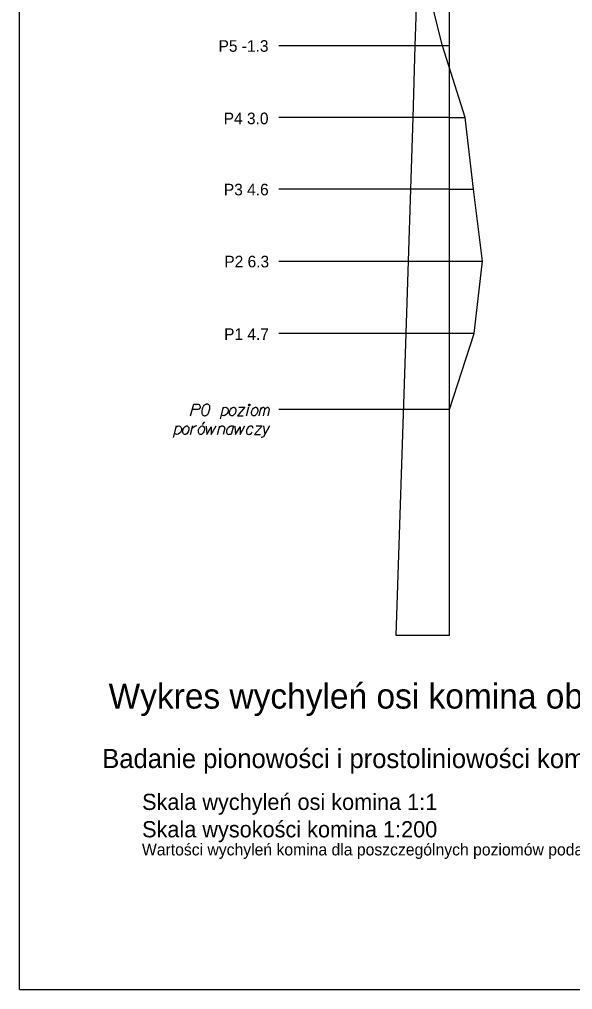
# Model space of a CAD drawing. Extents: x 138 to 6653, y -177 to 1520.
# Drawn here: x 377.01 to 387.51, y 2.29 to 20.71 of the extents above; entities that cross this region are included whole.
import ezdxf

# ---------------------------------------------------------------- set-up
doc = ezdxf.new("R2010")
doc.units = 0
for name, color, linetype in [('15 listopad 2008', 7, 'Continuous'), ('Opisy', 7, 'Continuous'), ('Ramka do drukowania', 7, 'Continuous'), ('Standart wykresów', 7, 'Continuous'), ('Wykresy 4 maj 2008', 7, 'Continuous')]:
    doc.layers.add(name, color=color, linetype=linetype)

msp = doc.modelspace()

# ---------------------------------------------------------------- linework, layer by layer
at = {"layer": '15 listopad 2008'}
msp.add_lwpolyline([(385.168, 13.297), (385.638, 14.742), (385.798, 16.118), (385.628, 17.485), (385.468, 18.843), (385.038, 20.202), (384.688, 21.593), (383.508, 22.995), (383.198, 23.989), (383.168, 24.969), (383.328, 25.428), (383.838, 25.945), (384.008, 26.413), (384.828, 26.981), (386.018, 27.507), (386.078, 27.694), (390.178, 28.392), (392.538, 28.755), (393.608, 29.011)], dxfattribs=at)
at = {"layer": 'Ramka do drukowania'}
for q in [(377.007, 31.985), (398.007, 2.285)]:
    msp.add_line((377.007, 2.285), q, dxfattribs=at)
at = {"layer": 'Standart wykresów'}
for p, q in [((385.168, 9.011), (385.168, 29.095)), ((384.521, 20.202), (384.565, 21.593)), ((385.038, 20.202), (381.931, 20.202)), ((384.478, 18.843), (384.521, 20.202)), ((385.168, 18.843), (381.931, 18.843)), ((384.436, 17.485), (384.478, 18.843)), ((385.168, 17.485), (381.931, 17.485)), ((384.394, 16.118), (384.436, 17.485)), ((385.168, 17.485), (385.628, 17.485)), ((381.931, 16.118), (385.168, 16.118)), ((384.349, 14.742), (384.394, 16.118)), ((385.168, 14.742), (381.931, 14.742)), ((384.161, 9.011), (384.349, 14.742)), ((385.168, 13.297), (381.931, 13.297)), ((385.168, 9.011), (384.161, 9.011))]:
    msp.add_line(p, q, dxfattribs=at)
for points in [[(380.257, 13.181), (380.316, 13.401), (380.39, 13.401), (380.4, 13.399), (380.406, 13.398), (380.416, 13.392), (380.423, 13.387), (380.428, 13.38), (380.433, 13.372), (380.437, 13.36), (380.439, 13.349), (380.437, 13.341), (380.435, 13.334), (380.432, 13.327), (380.428, 13.321), (380.423, 13.315), (380.416, 13.309), (380.411, 13.306), (380.402, 13.302), (380.394, 13.301), (380.29, 13.301)], [(380.572, 13.401), (380.568, 13.401), (380.558, 13.399), (380.551, 13.398), (380.546, 13.396), (380.537, 13.392), (380.527, 13.387), (380.518, 13.382), (380.51, 13.375), (380.504, 13.368), (380.499, 13.36), (380.494, 13.351), (380.489, 13.341), (380.485, 13.334), (380.482, 13.323), (380.477, 13.306), (380.471, 13.28), (380.468, 13.259), (380.468, 13.24), (380.47, 13.226), (380.477, 13.211), (380.482, 13.202), (380.491, 13.192), (380.501, 13.185), (380.506, 13.183), (380.517, 13.181), (380.525, 13.181), (380.539, 13.183), (380.551, 13.186), (380.56, 13.192), (380.572, 13.2), (380.577, 13.205), (380.584, 13.212), (380.589, 13.219), (380.593, 13.224), (380.596, 13.233), (380.598, 13.237), (380.601, 13.245), (380.605, 13.256), (380.608, 13.266), (380.61, 13.273), (380.612, 13.278), (380.614, 13.285), (380.617, 13.301), (380.619, 13.309), (380.62, 13.318), (380.622, 13.33), (380.624, 13.346), (380.624, 13.351), (380.622, 13.358), (380.62, 13.365), (380.615, 13.375), (380.61, 13.382), (380.605, 13.387), (380.598, 13.392), (380.591, 13.396), (380.586, 13.398), (380.581, 13.399), (380.572, 13.401)], [(380.823, 13.124), (380.882, 13.341)], [(380.877, 13.321), (380.894, 13.335), (380.92, 13.341), (380.941, 13.337), (380.955, 13.327), (380.965, 13.313), (380.972, 13.294), (380.974, 13.276), (380.97, 13.261), (380.965, 13.242), (380.951, 13.221), (380.934, 13.202), (380.908, 13.185), (380.885, 13.181), (380.865, 13.183), (380.842, 13.195)], [(381.071, 13.341), (381.083, 13.341), (381.097, 13.334), (381.111, 13.315), (381.112, 13.306), (381.114, 13.297), (381.114, 13.29), (381.114, 13.264), (381.109, 13.247), (381.1, 13.226), (381.09, 13.209), (381.073, 13.193), (381.057, 13.181), (381.031, 13.181), (381.021, 13.185), (381.01, 13.193), (381.005, 13.202), (380.998, 13.223), (380.998, 13.254), (381.002, 13.264), (381.008, 13.287), (381.015, 13.299), (381.019, 13.306), (381.036, 13.325), (381.053, 13.335), (381.071, 13.341)], [(381.175, 13.344), (381.287, 13.344), (381.144, 13.181), (381.254, 13.181)], [(381.317, 13.181), (381.362, 13.349)], [(381.365, 13.401), (381.374, 13.401), (381.379, 13.398), (381.384, 13.391), (381.384, 13.382), (381.379, 13.375), (381.374, 13.372), (381.365, 13.372), (381.36, 13.375), (381.355, 13.382), (381.355, 13.391), (381.36, 13.398), (381.365, 13.401)], [(381.487, 13.341), (381.499, 13.341), (381.513, 13.334), (381.526, 13.315), (381.528, 13.306), (381.53, 13.297), (381.53, 13.29), (381.53, 13.264), (381.525, 13.247), (381.516, 13.226), (381.506, 13.209), (381.488, 13.193), (381.473, 13.181), (381.447, 13.181), (381.436, 13.185), (381.426, 13.193), (381.421, 13.202), (381.414, 13.223), (381.414, 13.254), (381.417, 13.264), (381.424, 13.287), (381.431, 13.299), (381.435, 13.306), (381.452, 13.325), (381.469, 13.335), (381.487, 13.341)], [(381.559, 13.181), (381.599, 13.339)], [(381.589, 13.297), (381.597, 13.316), (381.606, 13.327), (381.616, 13.334), (381.627, 13.339), (381.634, 13.342), (381.644, 13.342), (381.648, 13.341), (381.655, 13.334), (381.661, 13.325), (381.667, 13.309), (381.668, 13.301), (381.677, 13.316), (381.687, 13.327), (381.698, 13.334), (381.708, 13.339), (381.717, 13.342), (381.726, 13.342), (381.732, 13.341), (381.738, 13.334), (381.743, 13.325), (381.748, 13.309), (381.75, 13.301), (381.72, 13.181)], [(381.639, 13.181), (381.668, 13.301)], [(379.933, 12.771), (379.992, 12.987)], [(379.987, 12.968), (380.005, 12.982), (380.031, 12.987), (380.051, 12.984), (380.065, 12.973), (380.076, 12.96), (380.082, 12.941), (380.084, 12.923), (380.081, 12.908), (380.076, 12.889), (380.062, 12.868), (380.044, 12.849), (380.018, 12.831), (379.996, 12.828), (379.975, 12.83), (379.953, 12.842)], [(380.181, 12.987), (380.193, 12.987), (380.207, 12.98), (380.221, 12.961), (380.223, 12.953), (380.225, 12.944), (380.225, 12.937), (380.225, 12.911), (380.219, 12.894), (380.211, 12.873), (380.2, 12.856), (380.183, 12.84), (380.167, 12.828), (380.141, 12.828), (380.131, 12.831), (380.121, 12.84), (380.115, 12.849), (380.108, 12.87), (380.108, 12.901), (380.112, 12.911), (380.119, 12.934), (380.126, 12.946), (380.129, 12.953), (380.147, 12.972), (380.164, 12.982), (380.181, 12.987)], [(380.254, 12.828), (380.297, 12.993)], [(380.287, 12.953), (380.296, 12.96), (380.315, 12.973), (380.335, 12.982), (380.351, 12.987), (380.375, 12.993)], [(380.477, 12.987), (380.49, 12.987), (380.503, 12.98), (380.517, 12.961), (380.519, 12.953), (380.521, 12.944), (380.521, 12.937), (380.521, 12.911), (380.515, 12.894), (380.507, 12.873), (380.496, 12.856), (380.479, 12.84), (380.464, 12.828), (380.438, 12.828), (380.427, 12.831), (380.417, 12.84), (380.412, 12.849), (380.405, 12.87), (380.405, 12.901), (380.408, 12.911), (380.415, 12.934), (380.422, 12.946), (380.425, 12.953), (380.443, 12.972), (380.46, 12.982), (380.477, 12.987)], [(380.521, 13.064), (380.477, 13.015)], [(380.55, 12.986), (380.564, 12.828), (380.647, 12.972), (380.649, 12.828), (380.741, 12.989)], [(380.77, 12.828), (380.813, 12.987)], [(380.803, 12.949), (380.808, 12.958), (380.815, 12.968), (380.82, 12.973), (380.827, 12.98), (380.834, 12.984), (380.843, 12.987), (380.852, 12.989), (380.858, 12.989), (380.867, 12.987), (380.874, 12.984), (380.881, 12.98), (380.888, 12.975), (380.895, 12.968), (380.898, 12.963), (380.902, 12.956), (380.905, 12.947), (380.874, 12.828)], [(381.065, 12.973), (381.052, 12.982), (381.023, 12.982), (381.006, 12.979), (380.975, 12.961), (380.949, 12.93), (380.936, 12.897), (380.935, 12.88), (380.936, 12.866), (380.942, 12.854), (380.952, 12.84), (380.964, 12.831), (380.983, 12.828), (380.997, 12.83), (381.011, 12.831), (381.03, 12.842)], [(381.068, 12.987), (381.026, 12.828)], [(381.098, 12.986), (381.111, 12.828), (381.195, 12.972), (381.196, 12.828), (381.288, 12.989)], [(381.441, 12.941), (381.439, 12.961), (381.43, 12.975), (381.42, 12.982), (381.399, 12.986), (381.38, 12.986), (381.356, 12.97), (381.337, 12.944), (381.323, 12.918), (381.318, 12.899), (381.318, 12.87), (381.319, 12.859), (381.326, 12.845), (381.342, 12.831), (381.359, 12.828), (381.378, 12.83), (381.389, 12.833), (381.411, 12.849), (381.428, 12.878)], [(381.501, 12.991), (381.614, 12.991), (381.47, 12.828), (381.581, 12.828)], [(381.754, 12.989), (381.666, 12.828), (381.638, 12.781), (381.631, 12.778), (381.622, 12.774), (381.605, 12.771), (381.598, 12.771)], [(381.643, 12.987), (381.666, 12.828)]]:
    msp.add_lwpolyline(points, dxfattribs=at)
at = {"layer": 'Wykresy 4 maj 2008'}
for p, q in [((385.168, 20.202), (385.038, 20.202)), ((385.168, 18.843), (385.468, 18.843)), ((385.168, 16.118), (385.798, 16.118)), ((385.638, 14.742), (385.168, 14.742))]:
    msp.add_line(p, q, dxfattribs=at)

# ---------------------------------------------------------------- texts
at = {"layer": 'Opisy'}
for s, height, p in [('Wykres wychyleń osi komina obserwowanych ze stanowiska 1002', 0.47516, (378.7, 7.621)), ('Badanie pionowości i prostoliniowości komina zakładu ceramicznego "Ceramika Stróże"', 0.36281, (378.58, 6.492)), ('Skala wychyleń osi komina 1:1', 0.30766, (379.336, 5.696)), ('Skala wysokości komina 1:200', 0.30766, (379.336, 5.176)), ('Wartości wychyleń komina dla poszczególnych poziomów podano w milimetrach', 0.22315, (379.333, 4.833))]:
    msp.add_text(s, height=height, dxfattribs=at).set_placement(p)
at = {"layer": 'Wykresy 4 maj 2008'}
for s, p in [('P5 -1.3', (380.787, 20.092)), ('P4 3.0', (380.885, 18.717)), ('P3 4.6', (380.888, 17.366)), ('P2 6.3', (380.897, 15.999)), ('P1 4.7', (380.893, 14.621))]:
    msp.add_text(s, height=0.22, dxfattribs=at).set_placement(p)

doc.saveas('drawing.dxf')
